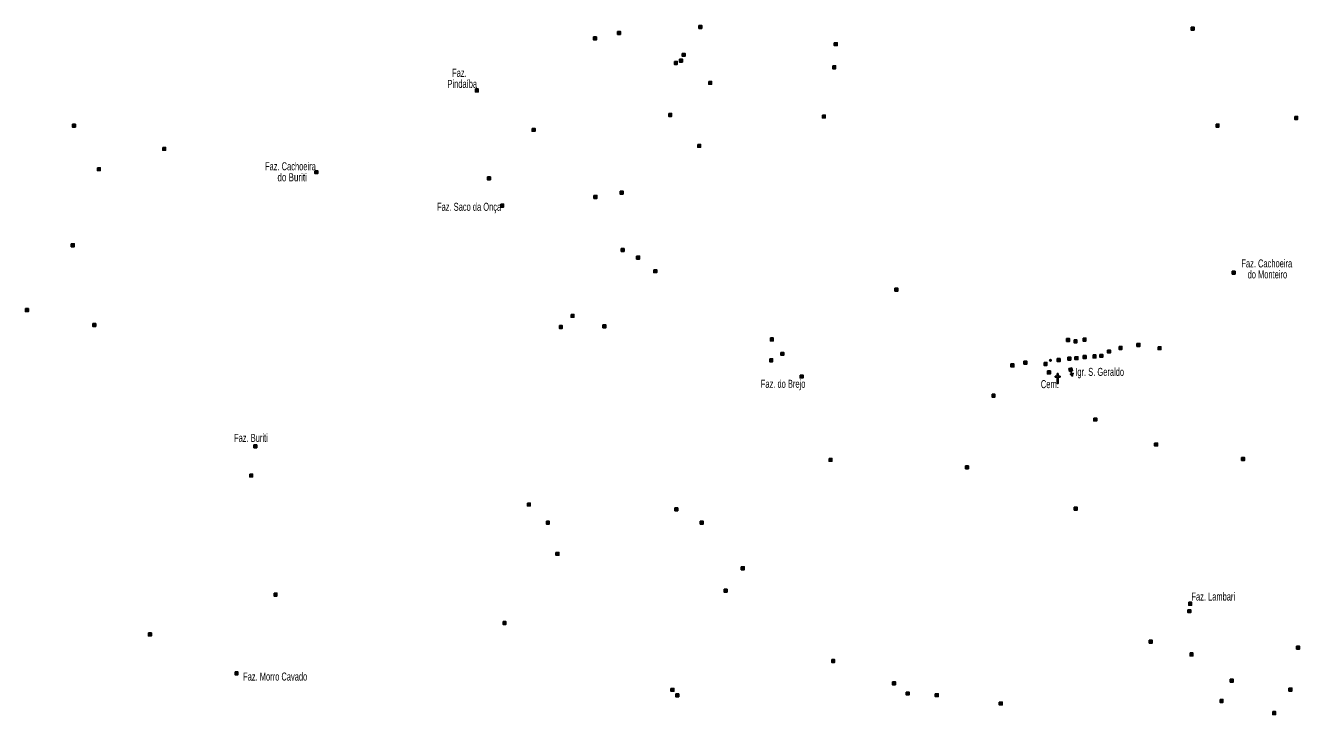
# Model space of a CAD drawing. Extents: x 447.8 to 473.9, y 7733.1 to 7760.8.
# Drawn here: x 461 to 473.74, y 7746.99 to 7753.87 of the extents above; entities that cross this region are included whole.
import ezdxf
from ezdxf.enums import TextEntityAlignment as Align

# ---------------------------------------------------------------- set-up
doc = ezdxf.new("R2010")
doc.units = 0
doc.header["$LTSCALE"] = 0.032
doc.header["$PDMODE"] = 32
doc.header["$PDSIZE"] = 0.016
for name, color, linetype, lineweight in [('2', 7, 'Continuous', 25), ('20', 7, 'Continuous', 25), ('6', 7, 'Continuous', 25)]:
    doc.layers.add(name, color=color, linetype=linetype, lineweight=lineweight)
doc.layers.add('61', color=7, linetype='Continuous')

msp = doc.modelspace()

# ---------------------------------------------------------------- hatches: boundary and pattern name
at = {"layer": '2'}
for points in [[(467.7343, 7753.8727), (467.7633, 7753.8727), (467.7633, 7753.8437), (467.7343, 7753.8437)], [(472.6526, 7753.8562), (472.6816, 7753.8562), (472.6816, 7753.8272), (472.6526, 7753.8272)], [(466.6814, 7753.7583), (466.7104, 7753.7583), (466.7104, 7753.7293), (466.6814, 7753.7293)], [(466.9217, 7753.8132), (466.9507, 7753.8132), (466.9507, 7753.7842), (466.9217, 7753.7842)], [(469.087, 7753.701), (469.116, 7753.701), (469.116, 7753.672), (469.087, 7753.672)], [(467.5672, 7753.5935), (467.5962, 7753.5935), (467.5962, 7753.5645), (467.5672, 7753.5645)], [(467.4894, 7753.5133), (467.5184, 7753.5133), (467.5184, 7753.4843), (467.4894, 7753.4843)], [(467.5397, 7753.5362), (467.5687, 7753.5362), (467.5687, 7753.5072), (467.5397, 7753.5072)], [(469.071, 7753.4699), (469.1, 7753.4699), (469.1, 7753.4409), (469.071, 7753.4409)], [(467.8327, 7753.3142), (467.8617, 7753.3142), (467.8617, 7753.2852), (467.8327, 7753.2852)], [(465.5004, 7753.2387), (465.5294, 7753.2387), (465.5294, 7753.2097), (465.5004, 7753.2097)], [(467.4322, 7752.9938), (467.4612, 7752.9938), (467.4612, 7752.9648), (467.4322, 7752.9648)], [(468.968, 7752.9778), (468.997, 7752.9778), (468.997, 7752.9488), (468.968, 7752.9488)], [(473.6878, 7752.9638), (473.7168, 7752.9638), (473.7168, 7752.9348), (473.6878, 7752.9348)], [(461.4743, 7752.8862), (461.5033, 7752.8862), (461.5033, 7752.8572), (461.4743, 7752.8572)], [(466.068, 7752.845), (466.097, 7752.845), (466.097, 7752.816), (466.068, 7752.816)], [(472.9018, 7752.8871), (472.9308, 7752.8871), (472.9308, 7752.8581), (472.9018, 7752.8581)], [(467.7228, 7752.6848), (467.7518, 7752.6848), (467.7518, 7752.6558), (467.7228, 7752.6558)], [(462.3761, 7752.655), (462.4051, 7752.655), (462.4051, 7752.626), (462.3761, 7752.626)], [(461.7237, 7752.4513), (461.7527, 7752.4513), (461.7527, 7752.4223), (461.7237, 7752.4223)], [(463.8972, 7752.4219), (463.9262, 7752.4219), (463.9262, 7752.3929), (463.8972, 7752.3929)], [(465.6217, 7752.3598), (465.6507, 7752.3598), (465.6507, 7752.3308), (465.6217, 7752.3308)], [(466.686, 7752.1744), (466.715, 7752.1744), (466.715, 7752.1454), (466.686, 7752.1454)], [(466.9469, 7752.2179), (466.9759, 7752.2179), (466.9759, 7752.1889), (466.9469, 7752.1889)], [(465.7542, 7752.0879), (465.7832, 7752.0879), (465.7832, 7752.0589), (465.7542, 7752.0589)], [(461.4628, 7751.6914), (461.4918, 7751.6914), (461.4918, 7751.6624), (461.4628, 7751.6624)], [(466.9584, 7751.6434), (466.9874, 7751.6434), (466.9874, 7751.6144), (466.9584, 7751.6144)], [(467.1117, 7751.5678), (467.1407, 7751.5678), (467.1407, 7751.5388), (467.1117, 7751.5388)], [(467.2834, 7751.4328), (467.3124, 7751.4328), (467.3124, 7751.4038), (467.2834, 7751.4038)], [(473.0637, 7751.4174), (473.0927, 7751.4174), (473.0927, 7751.3884), (473.0637, 7751.3884)], [(469.6935, 7751.2474), (469.7225, 7751.2474), (469.7225, 7751.2184), (469.6935, 7751.2184)], [(461.005, 7751.0437), (461.034, 7751.0437), (461.034, 7751.0147), (461.005, 7751.0147)], [(461.678, 7750.8949), (461.707, 7750.8949), (461.707, 7750.8659), (461.678, 7750.8659)], [(466.4571, 7750.9865), (466.4861, 7750.9865), (466.4861, 7750.9575), (466.4571, 7750.9575)], [(466.3404, 7750.8743), (466.3694, 7750.8743), (466.3694, 7750.8453), (466.3404, 7750.8453)], [(466.7753, 7750.8812), (466.8043, 7750.8812), (466.8043, 7750.8522), (466.7753, 7750.8522)], [(468.4484, 7750.7507), (468.4774, 7750.7507), (468.4774, 7750.7217), (468.4484, 7750.7217)], [(471.4087, 7750.7444), (471.4377, 7750.7444), (471.4377, 7750.7154), (471.4087, 7750.7154)], [(471.4833, 7750.7316), (471.5123, 7750.7316), (471.5123, 7750.7026), (471.4833, 7750.7026)], [(471.5727, 7750.7486), (471.6017, 7750.7486), (471.6017, 7750.7196), (471.5727, 7750.7196)], [(471.9327, 7750.6656), (471.9617, 7750.6656), (471.9617, 7750.6366), (471.9327, 7750.6366)], [(472.1116, 7750.6954), (472.1406, 7750.6954), (472.1406, 7750.6664), (472.1116, 7750.6664)], [(472.3225, 7750.6634), (472.3515, 7750.6634), (472.3515, 7750.6344), (472.3225, 7750.6344)], [(468.4415, 7750.5424), (468.4705, 7750.5424), (468.4705, 7750.5134), (468.4415, 7750.5134)], [(468.5537, 7750.6065), (468.5827, 7750.6065), (468.5827, 7750.5775), (468.5537, 7750.5775)], [(470.9827, 7750.5186), (471.0117, 7750.5186), (471.0117, 7750.4896), (470.9827, 7750.4896)], [(471.183, 7750.5058), (471.212, 7750.5058), (471.212, 7750.4768), (471.183, 7750.4768)], [(471.315, 7750.5442), (471.344, 7750.5442), (471.344, 7750.5152), (471.315, 7750.5152)], [(471.4215, 7750.5591), (471.4505, 7750.5591), (471.4505, 7750.5301), (471.4215, 7750.5301)], [(471.4918, 7750.5633), (471.5208, 7750.5633), (471.5208, 7750.5343), (471.4918, 7750.5343)], [(471.5749, 7750.574), (471.6039, 7750.574), (471.6039, 7750.545), (471.5749, 7750.545)], [(471.6729, 7750.5804), (471.7019, 7750.5804), (471.7019, 7750.5514), (471.6729, 7750.5514)], [(471.741, 7750.5868), (471.77, 7750.5868), (471.77, 7750.5578), (471.741, 7750.5578)], [(471.8177, 7750.6294), (471.8467, 7750.6294), (471.8467, 7750.6004), (471.8177, 7750.6004)], [(468.746, 7750.3799), (468.775, 7750.3799), (468.775, 7750.3509), (468.746, 7750.3509)], [(470.8528, 7750.4909), (470.8818, 7750.4909), (470.8818, 7750.4619), (470.8528, 7750.4619)], [(471.217, 7750.4206), (471.246, 7750.4206), (471.246, 7750.3916), (471.217, 7750.3916)], [(470.6633, 7750.1885), (470.6923, 7750.1885), (470.6923, 7750.1595), (470.6633, 7750.1595)], [(471.6806, 7749.9507), (471.7096, 7749.9507), (471.7096, 7749.9217), (471.6806, 7749.9217)], [(463.287, 7749.6818), (463.316, 7749.6818), (463.316, 7749.6528), (463.287, 7749.6528)], [(472.2884, 7749.7007), (472.3174, 7749.7007), (472.3174, 7749.6717), (472.2884, 7749.6717)], [(469.0344, 7749.5468), (469.0634, 7749.5468), (469.0634, 7749.5178), (469.0344, 7749.5178)], [(473.1574, 7749.5559), (473.1864, 7749.5559), (473.1864, 7749.5269), (473.1574, 7749.5269)], [(463.2458, 7749.3911), (463.2748, 7749.3911), (463.2748, 7749.3621), (463.2458, 7749.3621)], [(470.3991, 7749.4728), (470.4281, 7749.4728), (470.4281, 7749.4438), (470.3991, 7749.4438)], [(466.0204, 7749.1014), (466.0494, 7749.1014), (466.0494, 7749.0724), (466.0204, 7749.0724)], [(467.494, 7749.0524), (467.523, 7749.0524), (467.523, 7749.0234), (467.494, 7749.0234)], [(471.4854, 7749.0596), (471.5144, 7749.0596), (471.5144, 7749.0306), (471.4854, 7749.0306)], [(466.2099, 7748.9196), (466.2389, 7748.9196), (466.2389, 7748.8906), (466.2099, 7748.8906)], [(467.748, 7748.9196), (467.777, 7748.9196), (467.777, 7748.8906), (467.748, 7748.8906)], [(466.306, 7748.6083), (466.335, 7748.6083), (466.335, 7748.5793), (466.306, 7748.5793)], [(468.1577, 7748.4641), (468.1867, 7748.4641), (468.1867, 7748.4351), (468.1577, 7748.4351)], [(467.9861, 7748.2398), (468.0151, 7748.2398), (468.0151, 7748.2108), (467.9861, 7748.2108)], [(463.4885, 7748.2009), (463.5175, 7748.2009), (463.5175, 7748.1719), (463.4885, 7748.1719)], [(472.6292, 7748.1096), (472.6582, 7748.1096), (472.6582, 7748.0806), (472.6292, 7748.0806)], [(472.6207, 7748.0351), (472.6497, 7748.0351), (472.6497, 7748.0061), (472.6207, 7748.0061)], [(465.7773, 7747.9171), (465.8063, 7747.9171), (465.8063, 7747.8881), (465.7773, 7747.8881)], [(462.2342, 7747.8027), (462.2632, 7747.8027), (462.2632, 7747.7737), (462.2342, 7747.7737)], [(472.2352, 7747.7305), (472.2642, 7747.7305), (472.2642, 7747.7015), (472.2352, 7747.7015)], [(472.642, 7747.6027), (472.671, 7747.6027), (472.671, 7747.5737), (472.642, 7747.5737)], [(473.707, 7747.6709), (473.736, 7747.6709), (473.736, 7747.6419), (473.707, 7747.6419)], [(469.0618, 7747.5371), (469.0908, 7747.5371), (469.0908, 7747.5081), (469.0618, 7747.5081)], [(463.0994, 7747.4136), (463.1284, 7747.4136), (463.1284, 7747.3846), (463.0994, 7747.3846)], [(473.0445, 7747.3407), (473.0735, 7747.3407), (473.0735, 7747.3117), (473.0445, 7747.3117)], [(467.455, 7747.2488), (467.484, 7747.2488), (467.484, 7747.2198), (467.455, 7747.2198)], [(469.6684, 7747.3151), (469.6974, 7747.3151), (469.6974, 7747.2861), (469.6684, 7747.2861)], [(469.8057, 7747.2121), (469.8347, 7747.2121), (469.8347, 7747.1831), (469.8057, 7747.1831)], [(470.0964, 7747.1961), (470.1254, 7747.1961), (470.1254, 7747.1671), (470.0964, 7747.1671)], [(473.6303, 7747.2513), (473.6593, 7747.2513), (473.6593, 7747.2223), (473.6303, 7747.2223)], [(467.5031, 7747.1938), (467.5321, 7747.1938), (467.5321, 7747.1648), (467.5031, 7747.1648)], [(470.7357, 7747.1128), (470.7647, 7747.1128), (470.7647, 7747.0838), (470.7357, 7747.0838)], [(472.9423, 7747.1384), (472.9713, 7747.1384), (472.9713, 7747.1094), (472.9423, 7747.1094)], [(473.4684, 7747.017), (473.4974, 7747.017), (473.4974, 7746.988), (473.4684, 7746.988)]]:
    msp.add_hatch(color=256, dxfattribs=at).paths.add_polyline_path(points)
at = {"layer": '6'}
for points in [[(471.4679, 7750.4227), (471.4607, 7750.4518), (471.4315, 7750.4446), (471.4387, 7750.4155)], [(471.4509, 7750.4185), (471.4557, 7750.4198), (471.4623, 7750.393), (471.4745, 7750.396), (471.4756, 7750.3911), (471.4635, 7750.3882), (471.4677, 7750.3712), (471.4629, 7750.37), (471.4587, 7750.387), (471.4466, 7750.384), (471.4453, 7750.3888), (471.4574, 7750.3919)]]:
    msp.add_hatch(color=256, dxfattribs=at).paths.add_polyline_path(points)

# ---------------------------------------------------------------- linework, layer by layer
at = {"layer": '2'}
for points in [[(467.7343, 7753.8727), (467.7633, 7753.8727), (467.7633, 7753.8437), (467.7343, 7753.8437)], [(472.6526, 7753.8562), (472.6816, 7753.8562), (472.6816, 7753.8272), (472.6526, 7753.8272)], [(466.6814, 7753.7583), (466.7104, 7753.7583), (466.7104, 7753.7293), (466.6814, 7753.7293)], [(466.9217, 7753.8132), (466.9507, 7753.8132), (466.9507, 7753.7842), (466.9217, 7753.7842)], [(469.087, 7753.701), (469.116, 7753.701), (469.116, 7753.672), (469.087, 7753.672)], [(467.5672, 7753.5935), (467.5962, 7753.5935), (467.5962, 7753.5645), (467.5672, 7753.5645)], [(467.4894, 7753.5133), (467.5184, 7753.5133), (467.5184, 7753.4843), (467.4894, 7753.4843)], [(467.5397, 7753.5362), (467.5687, 7753.5362), (467.5687, 7753.5072), (467.5397, 7753.5072)], [(469.071, 7753.4699), (469.1, 7753.4699), (469.1, 7753.4409), (469.071, 7753.4409)], [(467.8327, 7753.3142), (467.8617, 7753.3142), (467.8617, 7753.2852), (467.8327, 7753.2852)], [(465.5004, 7753.2387), (465.5294, 7753.2387), (465.5294, 7753.2097), (465.5004, 7753.2097)], [(467.4322, 7752.9938), (467.4612, 7752.9938), (467.4612, 7752.9648), (467.4322, 7752.9648)], [(468.968, 7752.9778), (468.997, 7752.9778), (468.997, 7752.9488), (468.968, 7752.9488)], [(473.6878, 7752.9638), (473.7168, 7752.9638), (473.7168, 7752.9348), (473.6878, 7752.9348)], [(461.4743, 7752.8862), (461.5033, 7752.8862), (461.5033, 7752.8572), (461.4743, 7752.8572)], [(466.068, 7752.845), (466.097, 7752.845), (466.097, 7752.816), (466.068, 7752.816)], [(472.9018, 7752.8871), (472.9308, 7752.8871), (472.9308, 7752.8581), (472.9018, 7752.8581)], [(467.7228, 7752.6848), (467.7518, 7752.6848), (467.7518, 7752.6558), (467.7228, 7752.6558)], [(462.3761, 7752.655), (462.4051, 7752.655), (462.4051, 7752.626), (462.3761, 7752.626)], [(461.7237, 7752.4513), (461.7527, 7752.4513), (461.7527, 7752.4223), (461.7237, 7752.4223)], [(463.8972, 7752.4219), (463.9262, 7752.4219), (463.9262, 7752.3929), (463.8972, 7752.3929)], [(465.6217, 7752.3598), (465.6507, 7752.3598), (465.6507, 7752.3308), (465.6217, 7752.3308)], [(466.686, 7752.1744), (466.715, 7752.1744), (466.715, 7752.1454), (466.686, 7752.1454)], [(466.9469, 7752.2179), (466.9759, 7752.2179), (466.9759, 7752.1889), (466.9469, 7752.1889)], [(465.7542, 7752.0879), (465.7832, 7752.0879), (465.7832, 7752.0589), (465.7542, 7752.0589)], [(461.4628, 7751.6914), (461.4918, 7751.6914), (461.4918, 7751.6624), (461.4628, 7751.6624)], [(466.9584, 7751.6434), (466.9874, 7751.6434), (466.9874, 7751.6144), (466.9584, 7751.6144)], [(467.1117, 7751.5678), (467.1407, 7751.5678), (467.1407, 7751.5388), (467.1117, 7751.5388)], [(467.2834, 7751.4328), (467.3124, 7751.4328), (467.3124, 7751.4038), (467.2834, 7751.4038)], [(473.0637, 7751.4174), (473.0927, 7751.4174), (473.0927, 7751.3884), (473.0637, 7751.3884)], [(469.6935, 7751.2474), (469.7225, 7751.2474), (469.7225, 7751.2184), (469.6935, 7751.2184)], [(461.005, 7751.0437), (461.034, 7751.0437), (461.034, 7751.0147), (461.005, 7751.0147)], [(461.678, 7750.8949), (461.707, 7750.8949), (461.707, 7750.8659), (461.678, 7750.8659)], [(466.4571, 7750.9865), (466.4861, 7750.9865), (466.4861, 7750.9575), (466.4571, 7750.9575)], [(466.3404, 7750.8743), (466.3694, 7750.8743), (466.3694, 7750.8453), (466.3404, 7750.8453)], [(466.7753, 7750.8812), (466.8043, 7750.8812), (466.8043, 7750.8522), (466.7753, 7750.8522)], [(468.4484, 7750.7507), (468.4774, 7750.7507), (468.4774, 7750.7217), (468.4484, 7750.7217)], [(471.4087, 7750.7444), (471.4377, 7750.7444), (471.4377, 7750.7154), (471.4087, 7750.7154)], [(471.4833, 7750.7316), (471.5123, 7750.7316), (471.5123, 7750.7026), (471.4833, 7750.7026)], [(471.5727, 7750.7486), (471.6017, 7750.7486), (471.6017, 7750.7196), (471.5727, 7750.7196)], [(471.9327, 7750.6656), (471.9617, 7750.6656), (471.9617, 7750.6366), (471.9327, 7750.6366)], [(472.1116, 7750.6954), (472.1406, 7750.6954), (472.1406, 7750.6664), (472.1116, 7750.6664)], [(472.3225, 7750.6634), (472.3515, 7750.6634), (472.3515, 7750.6344), (472.3225, 7750.6344)], [(468.4415, 7750.5424), (468.4705, 7750.5424), (468.4705, 7750.5134), (468.4415, 7750.5134)], [(468.5537, 7750.6065), (468.5827, 7750.6065), (468.5827, 7750.5775), (468.5537, 7750.5775)], [(470.9827, 7750.5186), (471.0117, 7750.5186), (471.0117, 7750.4896), (470.9827, 7750.4896)], [(471.183, 7750.5058), (471.212, 7750.5058), (471.212, 7750.4768), (471.183, 7750.4768)], [(471.315, 7750.5442), (471.344, 7750.5442), (471.344, 7750.5152), (471.315, 7750.5152)], [(471.4215, 7750.5591), (471.4505, 7750.5591), (471.4505, 7750.5301), (471.4215, 7750.5301)], [(471.4918, 7750.5633), (471.5208, 7750.5633), (471.5208, 7750.5343), (471.4918, 7750.5343)], [(471.5749, 7750.574), (471.6039, 7750.574), (471.6039, 7750.545), (471.5749, 7750.545)], [(471.6729, 7750.5804), (471.7019, 7750.5804), (471.7019, 7750.5514), (471.6729, 7750.5514)], [(471.741, 7750.5868), (471.77, 7750.5868), (471.77, 7750.5578), (471.741, 7750.5578)], [(471.8177, 7750.6294), (471.8467, 7750.6294), (471.8467, 7750.6004), (471.8177, 7750.6004)], [(468.746, 7750.3799), (468.775, 7750.3799), (468.775, 7750.3509), (468.746, 7750.3509)], [(470.8528, 7750.4909), (470.8818, 7750.4909), (470.8818, 7750.4619), (470.8528, 7750.4619)], [(471.217, 7750.4206), (471.246, 7750.4206), (471.246, 7750.3916), (471.217, 7750.3916)], [(470.6633, 7750.1885), (470.6923, 7750.1885), (470.6923, 7750.1595), (470.6633, 7750.1595)], [(471.6806, 7749.9507), (471.7096, 7749.9507), (471.7096, 7749.9217), (471.6806, 7749.9217)], [(463.287, 7749.6818), (463.316, 7749.6818), (463.316, 7749.6528), (463.287, 7749.6528)], [(472.2884, 7749.7007), (472.3174, 7749.7007), (472.3174, 7749.6717), (472.2884, 7749.6717)], [(469.0344, 7749.5468), (469.0634, 7749.5468), (469.0634, 7749.5178), (469.0344, 7749.5178)], [(473.1574, 7749.5559), (473.1864, 7749.5559), (473.1864, 7749.5269), (473.1574, 7749.5269)], [(463.2458, 7749.3911), (463.2748, 7749.3911), (463.2748, 7749.3621), (463.2458, 7749.3621)], [(470.3991, 7749.4728), (470.4281, 7749.4728), (470.4281, 7749.4438), (470.3991, 7749.4438)], [(466.0204, 7749.1014), (466.0494, 7749.1014), (466.0494, 7749.0724), (466.0204, 7749.0724)], [(467.494, 7749.0524), (467.523, 7749.0524), (467.523, 7749.0234), (467.494, 7749.0234)], [(471.4854, 7749.0596), (471.5144, 7749.0596), (471.5144, 7749.0306), (471.4854, 7749.0306)], [(466.2099, 7748.9196), (466.2389, 7748.9196), (466.2389, 7748.8906), (466.2099, 7748.8906)], [(467.748, 7748.9196), (467.777, 7748.9196), (467.777, 7748.8906), (467.748, 7748.8906)], [(466.306, 7748.6083), (466.335, 7748.6083), (466.335, 7748.5793), (466.306, 7748.5793)], [(468.1577, 7748.4641), (468.1867, 7748.4641), (468.1867, 7748.4351), (468.1577, 7748.4351)], [(467.9861, 7748.2398), (468.0151, 7748.2398), (468.0151, 7748.2108), (467.9861, 7748.2108)], [(463.4885, 7748.2009), (463.5175, 7748.2009), (463.5175, 7748.1719), (463.4885, 7748.1719)], [(472.6292, 7748.1096), (472.6582, 7748.1096), (472.6582, 7748.0806), (472.6292, 7748.0806)], [(472.6207, 7748.0351), (472.6497, 7748.0351), (472.6497, 7748.0061), (472.6207, 7748.0061)], [(465.7773, 7747.9171), (465.8063, 7747.9171), (465.8063, 7747.8881), (465.7773, 7747.8881)], [(462.2342, 7747.8027), (462.2632, 7747.8027), (462.2632, 7747.7737), (462.2342, 7747.7737)], [(472.2352, 7747.7305), (472.2642, 7747.7305), (472.2642, 7747.7015), (472.2352, 7747.7015)], [(472.642, 7747.6027), (472.671, 7747.6027), (472.671, 7747.5737), (472.642, 7747.5737)], [(473.707, 7747.6709), (473.736, 7747.6709), (473.736, 7747.6419), (473.707, 7747.6419)], [(469.0618, 7747.5371), (469.0908, 7747.5371), (469.0908, 7747.5081), (469.0618, 7747.5081)], [(463.0994, 7747.4136), (463.1284, 7747.4136), (463.1284, 7747.3846), (463.0994, 7747.3846)], [(473.0445, 7747.3407), (473.0735, 7747.3407), (473.0735, 7747.3117), (473.0445, 7747.3117)], [(467.455, 7747.2488), (467.484, 7747.2488), (467.484, 7747.2198), (467.455, 7747.2198)], [(469.6684, 7747.3151), (469.6974, 7747.3151), (469.6974, 7747.2861), (469.6684, 7747.2861)], [(469.8057, 7747.2121), (469.8347, 7747.2121), (469.8347, 7747.1831), (469.8057, 7747.1831)], [(470.0964, 7747.1961), (470.1254, 7747.1961), (470.1254, 7747.1671), (470.0964, 7747.1671)], [(473.6303, 7747.2513), (473.6593, 7747.2513), (473.6593, 7747.2223), (473.6303, 7747.2223)], [(467.5031, 7747.1938), (467.5321, 7747.1938), (467.5321, 7747.1648), (467.5031, 7747.1648)], [(470.7357, 7747.1128), (470.7647, 7747.1128), (470.7647, 7747.0838), (470.7357, 7747.0838)], [(472.9423, 7747.1384), (472.9713, 7747.1384), (472.9713, 7747.1094), (472.9423, 7747.1094)], [(473.4684, 7747.017), (473.4974, 7747.017), (473.4974, 7746.988), (473.4684, 7746.988)]]:
    msp.add_lwpolyline(points, close=True, dxfattribs=at)
at = {"layer": '20'}
for points in [[(471.3232, 7750.3673), (471.3232, 7750.3953), (471.3152, 7750.3953), (471.3152, 7750.3673)], [(471.3152, 7750.3673), (471.2952, 7750.3673), (471.2952, 7750.3588), (471.3152, 7750.3588), (471.3152, 7750.2953)], [(471.3152, 7750.2953), (471.3232, 7750.2953), (471.3232, 7750.3588)], [(471.3232, 7750.3588), (471.3432, 7750.3588), (471.3432, 7750.3673), (471.3232, 7750.3673)]]:
    msp.add_lwpolyline(points, dxfattribs=at)
msp.add_point((471.247, 7750.5262), dxfattribs=at)
at = {"layer": '6'}
for points in [[(471.4679, 7750.4227), (471.4607, 7750.4518), (471.4315, 7750.4446), (471.4387, 7750.4155)], [(471.4509, 7750.4185), (471.4557, 7750.4198), (471.4623, 7750.393), (471.4745, 7750.396), (471.4756, 7750.3911), (471.4635, 7750.3882), (471.4677, 7750.3712), (471.4629, 7750.37), (471.4587, 7750.387), (471.4466, 7750.384), (471.4453, 7750.3888), (471.4574, 7750.3919)]]:
    msp.add_lwpolyline(points, close=True, dxfattribs=at)

# ---------------------------------------------------------------- texts
at = {"layer": '61'}
for s, width, p in [('  Faz.     ', 0.7, (465.5174, 7753.3596)), ('Pindaíba', 0.7, (465.5174, 7753.2496)), ('Faz. Cachoeira', 0.7, (463.9062, 7752.4259)), ('    do Buriti    ', 0.75, (463.9062, 7752.3159)), ('Faz. Saco da Onça', 0.7, (465.7583, 7752.0212)), ('Faz. do Brejo', 0.7, (468.7986, 7750.2523)), ('Cem.', 0.65, (471.3313, 7750.2491))]:
    msp.add_text(s, height=0.08, dxfattribs=dict(at, width=width)).set_placement(p, align=Align.RIGHT)
at = {"layer": '61', "width": 0.7}
for s, p in [('Faz. Cachoeira', (473.1548, 7751.4555)), ('   do Monteiro  ', (473.1548, 7751.3455)), ('Igr. S. Geraldo', (471.4956, 7750.3717)), ('Faz. Buriti', (463.089, 7749.7122)), ('Faz. Lambari', (472.6557, 7748.1267)), ('Faz. Morro Cavado', (463.1797, 7747.3273))]:
    msp.add_text(s, height=0.08, dxfattribs=at).set_placement(p)

doc.saveas('drawing.dxf')
